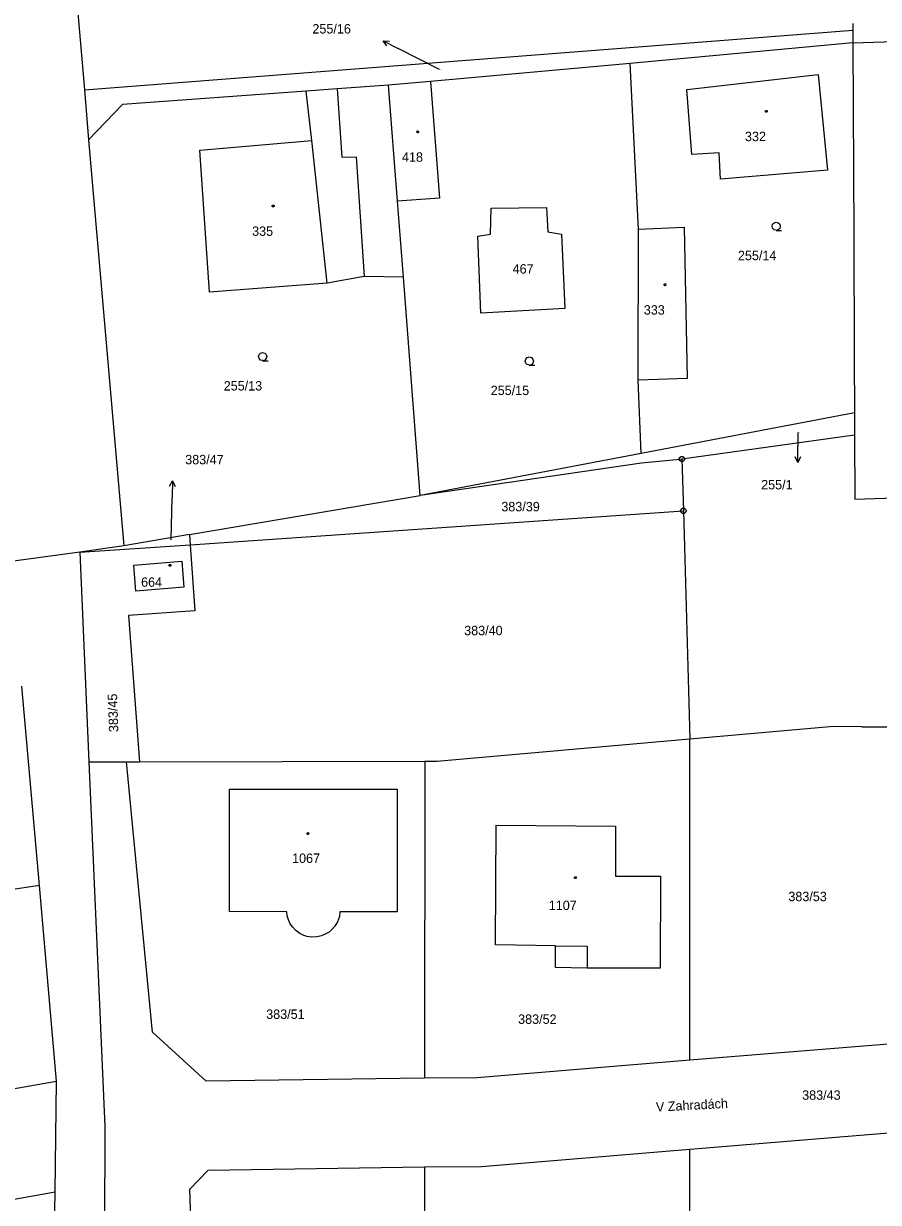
# Model space of a CAD drawing. Extents: x -757994 to -755874, y -1047691 to -1046119.
# Drawn here: x -757448.7 to -757371.4, y -1047587.6 to -1047481 of the extents above; entities that cross this region are included whole.
import ezdxf

# ---------------------------------------------------------------- set-up
doc = ezdxf.new("R2010")
doc.units = 0
doc.layers.add('katastrální mapa', color=7, linetype='Continuous')

msp = doc.modelspace()

# ---------------------------------------------------------------- linework, layer by layer
at = {"layer": 'katastrální mapa'}
for p, q in [((-757444.05, -1047476.64), (-757443.16, -1047486.98)), ((-757443.16, -1047486.98), (-757373.68, -1047481.59)), ((-757373.69, -1047480.99), (-757373.68, -1047481.59)), ((-757373.68, -1047481.59), (-757373.67, -1047482.73)), ((-757416.14, -1047482.56), (-757414.8, -1047483.24)), ((-757373.67, -1047482.73), (-757393.82, -1047484.61)), ((-757373.67, -1047482.73), (-757352.65, -1047482.07)), ((-757373.67, -1047482.73), (-757373.6, -1047500.09)), ((-757411.06, -1047485.14), (-757414.8, -1047483.24)), ((-757393.82, -1047484.61), (-757411.87, -1047486.22)), ((-757393.05, -1047499.58), (-757393.82, -1047484.61)), ((-757388.69, -1047486.94), (-757376.8, -1047485.6)), ((-757376.8, -1047485.6), (-757375.98, -1047494.24)), ((-757443.16, -1047486.98), (-757442.77, -1047491.49)), ((-757420.29, -1047486.9), (-757423.11, -1047487.1)), ((-757415.65, -1047486.56), (-757420.29, -1047486.9)), ((-757420.29, -1047486.9), (-757419.89, -1047493.06)), ((-757411.87, -1047486.22), (-757415.65, -1047486.56)), ((-757414.84, -1047497.06), (-757415.65, -1047486.56)), ((-757411.87, -1047486.22), (-757411.05, -1047496.77)), ((-757388.23, -1047492.83), (-757388.69, -1047486.94)), ((-757423.11, -1047487.1), (-757439.72, -1047488.3)), ((-757422.59, -1047491.55), (-757423.11, -1047487.1)), ((-757439.72, -1047488.3), (-757442.77, -1047491.49)), ((-757442.77, -1047491.49), (-757439.6, -1047528.2)), ((-757432.72, -1047492.42), (-757422.59, -1047491.55)), ((-757421.2, -1047504.45), (-757422.59, -1047491.55)), ((-757431.85, -1047505.28), (-757432.72, -1047492.42)), ((-757419.89, -1047493.06), (-757418.57, -1047493.04)), ((-757418.57, -1047493.04), (-757417.86, -1047503.85)), ((-757385.78, -1047492.69), (-757388.23, -1047492.83)), ((-757385.63, -1047495.06), (-757385.78, -1047492.69)), ((-757375.98, -1047494.24), (-757385.63, -1047495.06)), ((-757411.05, -1047496.77), (-757414.84, -1047497.06)), ((-757414.32, -1047503.91), (-757414.84, -1047497.06)), ((-757406.39, -1047497.69), (-757401.37, -1047497.62)), ((-757401.37, -1047497.62), (-757401.25, -1047499.83)), ((-757406.44, -1047500.02), (-757406.39, -1047497.69)), ((-757393.08, -1047513.22), (-757393.05, -1047499.58)), ((-757393.05, -1047499.58), (-757388.94, -1047499.4)), ((-757388.94, -1047499.4), (-757388.66, -1047513.06)), ((-757407.58, -1047500.22), (-757406.44, -1047500.02)), ((-757407.32, -1047507.17), (-757407.58, -1047500.22)), ((-757401.25, -1047499.83), (-757400.03, -1047500.04)), ((-757400.03, -1047500.04), (-757399.71, -1047506.76)), ((-757373.6, -1047500.09), (-757373.55, -1047511.19)), ((-757417.86, -1047503.85), (-757421.2, -1047504.45)), ((-757414.32, -1047503.91), (-757417.86, -1047503.85)), ((-757412.8, -1047523.66), (-757414.32, -1047503.91)), ((-757421.2, -1047504.45), (-757431.85, -1047505.28)), ((-757399.71, -1047506.76), (-757407.32, -1047507.17)), ((-757373.55, -1047511.19), (-757373.53, -1047516.19)), ((-757388.66, -1047513.06), (-757393.08, -1047513.22)), ((-757392.81, -1047519.86), (-757393.08, -1047513.22)), ((-757373.53, -1047516.19), (-757392.81, -1047519.86)), ((-757373.53, -1047516.19), (-757373.52, -1047518.19)), ((-757373.52, -1047518.19), (-757389.13, -1047520.36)), ((-757378.65, -1047517.96), (-757378.65, -1047519.17)), ((-757373.52, -1047518.19), (-757373.51, -1047523.99)), ((-757392.81, -1047519.86), (-757412.8, -1047523.66)), ((-757378.65, -1047520.67), (-757378.65, -1047519.17)), ((-757392.78, -1047520.74), (-757412.8, -1047523.66)), ((-757389.31, -1047520.39), (-757392.78, -1047520.74)), ((-757389.13, -1047520.36), (-757389.31, -1047520.39)), ((-757389.19, -1047520.36), (-757389.07, -1047520.36)), ((-757389.13, -1047520.36), (-757389, -1047525.05)), ((-757435.2, -1047522.33), (-757435.23, -1047523.83)), ((-757435.32, -1047527.65), (-757435.23, -1047523.83)), ((-757433.65, -1047527.19), (-757412.8, -1047523.66)), ((-757373.51, -1047523.99), (-757366.05, -1047523.75)), ((-757433.59, -1047528.1), (-757389, -1047525.05)), ((-757389.06, -1047525.05), (-757388.94, -1047525.05)), ((-757389, -1047525.05), (-757388.43, -1047545.65)), ((-757433.65, -1047527.19), (-757439.6, -1047528.2)), ((-757433.65, -1047527.19), (-757433.59, -1047528.1)), ((-757443.57, -1047528.78), (-757433.59, -1047528.1)), ((-757439.6, -1047528.2), (-757443.57, -1047528.78)), ((-757433.59, -1047528.1), (-757433.18, -1047534.08)), ((-757443.57, -1047528.78), (-757449.79, -1047529.61)), ((-757443.57, -1047528.78), (-757442.75, -1047547.73)), ((-757438.7, -1047529.94), (-757434.35, -1047529.58)), ((-757434.35, -1047529.58), (-757434.16, -1047531.93)), ((-757438.51, -1047532.29), (-757438.7, -1047529.94)), ((-757434.16, -1047531.93), (-757438.51, -1047532.29)), ((-757433.18, -1047534.08), (-757439.17, -1047534.49)), ((-757439.17, -1047534.49), (-757438.16, -1047547.72)), ((-757447.2, -1047558.89), (-757448.82, -1047540.88)), ((-757388.43, -1047545.65), (-757375.77, -1047544.54)), ((-757372.86, -1047544.55), (-757375.77, -1047544.54)), ((-757372.86, -1047544.55), (-757364.41, -1047544.57)), ((-757411.29, -1047547.66), (-757388.43, -1047545.65)), ((-757388.43, -1047574.7), (-757388.43, -1047545.65)), ((-757442.75, -1047547.73), (-757439.35, -1047547.72)), ((-757442.75, -1047547.73), (-757441.32, -1047580.7)), ((-757437.01, -1047572.16), (-757439.35, -1047547.72)), ((-757439.35, -1047547.72), (-757438.16, -1047547.72)), ((-757438.16, -1047547.72), (-757412.39, -1047547.66)), ((-757412.39, -1047547.66), (-757412.42, -1047576.33)), ((-757412.39, -1047547.66), (-757411.29, -1047547.66)), ((-757405.98, -1047564.26), (-757405.93, -1047553.46)), ((-757405.93, -1047553.46), (-757395.13, -1047553.53)), ((-757395.13, -1047553.53), (-757395.14, -1047558.06)), ((-757395.14, -1047558.06), (-757391.08, -1047558.07)), ((-757391.08, -1047558.07), (-757391.11, -1047566.39)), ((-757447.2, -1047558.89), (-757479.77, -1047563.91)), ((-757445.67, -1047576.6), (-757447.2, -1047558.89)), ((-757400.55, -1047564.35), (-757405.98, -1047564.26)), ((-757400.55, -1047566.3), (-757400.55, -1047564.35)), ((-757400.55, -1047564.35), (-757397.71, -1047564.39)), ((-757397.71, -1047564.39), (-757397.71, -1047566.37)), ((-757397.71, -1047566.37), (-757400.55, -1047566.3)), ((-757391.11, -1047566.39), (-757397.71, -1047566.37)), ((-757432.16, -1047576.59), (-757437.01, -1047572.16)), ((-757364.43, -1047572.75), (-757388.43, -1047574.7)), ((-757388.43, -1047574.7), (-757407.65, -1047576.28)), ((-757412.42, -1047576.33), (-757432.16, -1047576.59)), ((-757407.65, -1047576.28), (-757412.42, -1047576.33)), ((-757472.57, -1047581.21), (-757445.67, -1047576.6)), ((-757445.8, -1047586.62), (-757445.67, -1047576.6)), ((-757441.32, -1047580.7), (-757441.38, -1047614.87)), ((-757388.42, -1047582.73), (-757364.44, -1047580.78)), ((-757407.25, -1047584.29), (-757388.42, -1047582.73)), ((-757388.41, -1047611.79), (-757388.42, -1047582.73)), ((-757433.62, -1047586.35), (-757431.98, -1047584.63)), ((-757431.98, -1047584.63), (-757412.42, -1047584.33)), ((-757412.42, -1047584.33), (-757407.25, -1047584.29)), ((-757412.42, -1047584.33), (-757412.4, -1047613.85)), ((-757445.8, -1047586.62), (-757473.85, -1047591.63)), ((-757446.18, -1047610.35), (-757445.8, -1047586.62)), ((-757433.39, -1047592.58), (-757433.62, -1047586.35))]:
    msp.add_line(p, q, dxfattribs=at)
for points in [[(-757415.81, -1047483.01), (-757416.14, -1047482.56), (-757415.58, -1047482.57)], [(-757380.61, -1047499.68), (-757380.8, -1047499.63), (-757380.94, -1047499.5), (-757380.98, -1047499.31), (-757380.94, -1047499.12), (-757380.8, -1047498.99), (-757380.61, -1047498.94), (-757380.43, -1047498.99), (-757380.29, -1047499.12), (-757380.24, -1047499.32), (-757380.29, -1047499.51), (-757380.43, -1047499.64), (-757380.62, -1047499.69), (-757380.12, -1047499.69)], [(-757427.03, -1047511.46), (-757427.22, -1047511.41), (-757427.35, -1047511.27), (-757427.41, -1047511.09), (-757427.35, -1047510.91), (-757427.22, -1047510.77), (-757427.04, -1047510.72), (-757426.85, -1047510.77), (-757426.72, -1047510.91), (-757426.67, -1047511.1), (-757426.72, -1047511.28), (-757426.85, -1047511.42), (-757427.04, -1047511.47), (-757426.54, -1047511.47)], [(-757402.92, -1047511.87), (-757403.11, -1047511.82), (-757403.25, -1047511.69), (-757403.3, -1047511.5), (-757403.25, -1047511.32), (-757403.11, -1047511.18), (-757402.93, -1047511.13), (-757402.74, -1047511.18), (-757402.6, -1047511.32), (-757402.56, -1047511.51), (-757402.6, -1047511.7), (-757402.74, -1047511.83), (-757402.93, -1047511.88), (-757402.43, -1047511.88)], [(-757378.4, -1047520.17), (-757378.65, -1047520.67), (-757378.9, -1047520.17)], [(-757435.46, -1047522.82), (-757435.2, -1047522.33), (-757434.96, -1047522.84)], [(-757424.86, -1047561.28), (-757430.05, -1047561.26), (-757430.03, -1047550.2), (-757414.87, -1047550.21), (-757414.89, -1047561.27), (-757420.05, -1047561.27)], [(-757423.33, -1047563.41), (-757423.69, -1047563.23), (-757424.04, -1047562.97), (-757424.32, -1047562.67), (-757424.54, -1047562.36), (-757424.7, -1047562.02), (-757424.81, -1047561.65), (-757424.86, -1047561.28)], [(-757420.05, -1047561.27), (-757420.1, -1047561.71), (-757420.27, -1047562.19), (-757420.5, -1047562.57), (-757420.74, -1047562.86), (-757421.04, -1047563.11), (-757421.38, -1047563.31), (-757421.73, -1047563.45)], [(-757421.73, -1047563.45), (-757422.14, -1047563.55), (-757422.62, -1047563.57), (-757423.04, -1047563.5), (-757423.19, -1047563.46), (-757423.33, -1047563.41)]]:
    msp.add_lwpolyline(points, dxfattribs=at)
for points in [[(-757381.51, -1047488.84), (-757381.46, -1047488.85), (-757381.44, -1047488.89), (-757381.43, -1047488.92), (-757381.44, -1047488.97), (-757381.48, -1047489), (-757381.51, -1047489.01), (-757381.55, -1047488.99), (-757381.59, -1047488.96), (-757381.6, -1047488.92), (-757381.59, -1047488.88), (-757381.54, -1047488.84)], [(-757413.02, -1047490.7), (-757412.97, -1047490.71), (-757412.95, -1047490.75), (-757412.94, -1047490.78), (-757412.95, -1047490.83), (-757412.99, -1047490.86), (-757413.02, -1047490.87), (-757413.07, -1047490.85), (-757413.1, -1047490.82), (-757413.1, -1047490.78), (-757413.1, -1047490.74), (-757413.05, -1047490.7)], [(-757426.09, -1047497.4), (-757426.04, -1047497.41), (-757426.01, -1047497.45), (-757426, -1047497.48), (-757426.01, -1047497.52), (-757426.05, -1047497.56), (-757426.09, -1047497.57), (-757426.14, -1047497.55), (-757426.17, -1047497.52), (-757426.18, -1047497.48), (-757426.17, -1047497.44), (-757426.12, -1047497.4)], [(-757390.65, -1047504.51), (-757390.6, -1047504.52), (-757390.58, -1047504.57), (-757390.57, -1047504.6), (-757390.58, -1047504.65), (-757390.61, -1047504.68), (-757390.65, -1047504.69), (-757390.7, -1047504.67), (-757390.73, -1047504.64), (-757390.74, -1047504.6), (-757390.73, -1047504.55), (-757390.69, -1047504.52)], [(-757389.05, -1047520.12), (-757388.93, -1047520.21), (-757388.88, -1047520.36), (-757388.93, -1047520.5), (-757389.05, -1047520.59), (-757389.21, -1047520.59), (-757389.34, -1047520.5), (-757389.39, -1047520.36), (-757389.34, -1047520.21), (-757389.21, -1047520.12)], [(-757388.93, -1047524.81), (-757388.8, -1047524.9), (-757388.75, -1047525.05), (-757388.8, -1047525.19), (-757388.93, -1047525.28), (-757389.08, -1047525.28), (-757389.21, -1047525.19), (-757389.26, -1047525.05), (-757389.21, -1047524.9), (-757389.08, -1047524.81)], [(-757435.41, -1047529.88), (-757435.36, -1047529.89), (-757435.34, -1047529.93), (-757435.33, -1047529.96), (-757435.34, -1047530), (-757435.38, -1047530.04), (-757435.41, -1047530.04), (-757435.46, -1047530.03), (-757435.49, -1047530), (-757435.5, -1047529.96), (-757435.49, -1047529.92), (-757435.45, -1047529.88)], [(-757422.95, -1047554.12), (-757422.9, -1047554.14), (-757422.88, -1047554.18), (-757422.86, -1047554.21), (-757422.88, -1047554.25), (-757422.92, -1047554.29), (-757422.95, -1047554.29), (-757422.99, -1047554.28), (-757423.02, -1047554.25), (-757423.03, -1047554.21), (-757423.02, -1047554.17), (-757422.98, -1047554.13)], [(-757398.75, -1047558.11), (-757398.7, -1047558.12), (-757398.68, -1047558.16), (-757398.67, -1047558.19), (-757398.68, -1047558.23), (-757398.72, -1047558.27), (-757398.75, -1047558.27), (-757398.79, -1047558.26), (-757398.83, -1047558.23), (-757398.84, -1047558.19), (-757398.83, -1047558.15), (-757398.78, -1047558.11)]]:
    msp.add_lwpolyline(points, close=True, dxfattribs=at)

# ---------------------------------------------------------------- texts
for s, height, p in [('255/16', 0.85, (-757422.54, -1047481.89)), ('255/16', 0.05, (-757411.05, -1047485.14)), ('332', 0.85, (-757383.43, -1047491.62)), ('418', 0.85, (-757414.44, -1047493.48)), ('335', 0.85, (-757427.99, -1047500.18)), ('255/14', 0.85, (-757384.07, -1047502.38)), ('467', 0.85, (-757404.44, -1047503.59)), ('333', 0.85, (-757392.58, -1047507.3)), ('255/13', 0.85, (-757430.56, -1047514.16)), ('255/15', 0.85, (-757406.42, -1047514.57)), ('255/1', 0.05, (-757378.64, -1047517.96)), ('383/47', 0.85, (-757434.04, -1047520.83)), ('255/1', 0.85, (-757381.97, -1047523.1)), ('383/39', 0.85, (-757405.46, -1047525.08)), ('383/47', 0.05, (-757435.31, -1047527.65)), ('664', 0.85, (-757438.03, -1047531.9)), ('383/40', 0.85, (-757408.82, -1047536.28)), ('1067', 0.85, (-757424.38, -1047556.86)), ('383/53', 0.85, (-757379.51, -1047560.32)), ('1107', 0.85, (-757401.17, -1047561.12)), ('383/51', 0.85, (-757426.72, -1047570.96)), ('383/52', 0.85, (-757403.94, -1047571.41)), ('383/43', 0.85, (-757378.26, -1047578.27))]:
    msp.add_text(s, height=height, dxfattribs=at).set_placement(p)
for s, rotation, p in [('383/45', 92.0743, (-757440.08, -1047545.02)), ('V Zahradách', 3.0367, (-757391.46, -1047579.35))]:
    msp.add_text(s, height=0.85, rotation=rotation, dxfattribs=at).set_placement(p)

doc.saveas('drawing.dxf')
